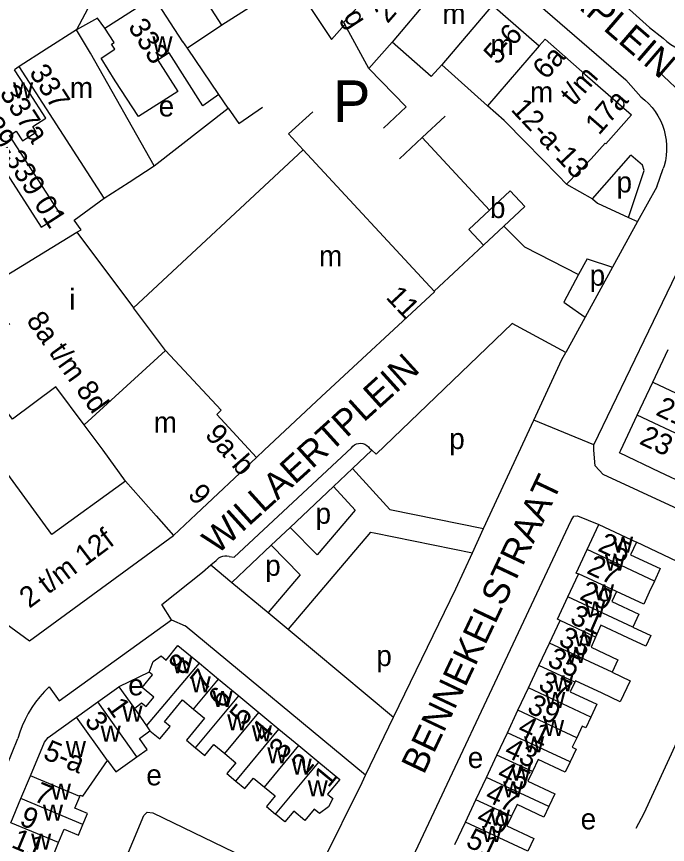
# Model space of a CAD drawing. Extents: x 159045 to 160918, y 380454 to 382516.
# Drawn here: x 160089.8 to 160214.7, y 381424.4 to 381583.2 of the extents above; entities that cross this region are included whole.
import ezdxf

# ---------------------------------------------------------------- set-up
doc = ezdxf.new("R2010")
doc.units = 0
for name, color, linetype in [('BLT_Basislijn', 7, 'Continuous'), ('BLT_Bebouwing', 7, 'Continuous'), ('BLT_Centroide', 7, 'Continuous'), ('BLT_Huisnummer', 7, 'Continuous'), ('BLT_Huisnummer_ tussenligend', 7, 'Continuous'), ('BLT_Huisnummer_reeks', 7, 'Continuous'), ('BLT_Onderverdeling_panden', 7, 'Continuous'), ('BLT_Straatnaam', 7, 'Continuous'), ('BLT_Tekst_parkeren', 7, 'Continuous'), ('BLT_Vlakafsluiter', 7, 'Continuous')]:
    doc.layers.add(name, color=color, linetype=linetype)

msp = doc.modelspace()

# ---------------------------------------------------------------- linework, layer by layer
at = {"layer": 'BLT_Basislijn'}
for p, q in [((160157.41, 381613.8), (160206.67, 381571.07)), ((160204.13, 381587.53), (160211.24, 381581.13)), ((160129.19, 381581.56), (160122.6, 381577.15)), ((160211.24, 381581.13), (160213.86, 381579.05)), ((160090.36, 381573.63), (160089.43, 381573.02)), ((160157.41, 381573.25), (160164.57, 381565.9)), ((160212.8, 381572.8), (160219.11, 381566.84)), ((160206.67, 381571.07), (160209.56, 381567.81)), ((160130.4, 381565.65), (160128.65, 381568.24)), ((160116.19, 381554.56), (160130.4, 381565.65)), ((160164.57, 381565.9), (160160.18, 381561.81)), ((160172.02, 381564.1), (160167.63, 381560.01)), ((160167.63, 381560.01), (160163.24, 381555.92)), ((160180.54, 381546.07), (160167.63, 381560.01)), ((160200.29, 381548.23), (160207.63, 381556.64)), ((160212.61, 381550.57), (160213.85, 381554.04)), ((160195.29, 381551.04), (160200.29, 381548.23)), ((160212.61, 381550.57), (160208.94, 381543.89)), ((160208.94, 381543.89), (160204.15, 381535.17)), ((160207.21, 381544.68), (160208.94, 381543.89)), ((160174.57, 381534.87), (160179.37, 381539.35)), ((160199.27, 381536.71), (160197.59, 381533.74)), ((160204.15, 381535.17), (160198.87, 381525.53)), ((160199.27, 381536.71), (160204.15, 381535.17)), ((160169.89, 381530.52), (160174.57, 381534.87)), ((160197.59, 381533.74), (160194.79, 381528.42)), ((160194.79, 381528.42), (160195.24, 381528.1)), ((160195.24, 381528.1), (160198.87, 381525.53)), ((160198.87, 381525.53), (160195.16, 381518.78)), ((160179.41, 381484.97), (160189.04, 381505.8)), ((160154.04, 381500.5), (160131.59, 381479.5)), ((160157.46, 381500.48), (160157.98, 381500.01)), ((160157.98, 381500.01), (160154.25, 381496.49)), ((160157.98, 381500.01), (160158.77, 381499.28)), ((160154.25, 381496.49), (160150.61, 381493.06)), ((160154.25, 381496.49), (160161.4, 381488.64)), ((160150.61, 381493.06), (160142.3, 381485.22)), ((160161.4, 381488.64), (160179.41, 381484.97)), ((160142.3, 381485.22), (160138.66, 381481.79)), ((160142.3, 381485.22), (160147.47, 381479.95)), ((160177.25, 381480.31), (160179.41, 381484.97)), ((160157.71, 381484.29), (160149.79, 381474.95)), ((160157.71, 381484.29), (160158.43, 381484.14)), ((160158.43, 381484.14), (160177.25, 381480.31)), ((160138.66, 381481.79), (160131.1, 381474.67)), ((160138.66, 381481.79), (160144.22, 381476.12)), ((160130.61, 381479.62), (160131.59, 381479.5)), ((160127.1, 381478), (160128.14, 381478.88)), ((160127.1, 381478), (160131.1, 381474.67)), ((160144.22, 381476.12), (160138.07, 381468.86)), ((160149.79, 381474.95), (160141.92, 381465.66)), ((160131.1, 381474.67), (160138.07, 381468.86)), ((160138.07, 381468.86), (160141.92, 381465.66)), ((160119.55, 381467.48), (160122.14, 381466.34)), ((160156.74, 381437.68), (160122.14, 381466.34)), ((160141.92, 381465.66), (160162.14, 381448.82)), ((160115.27, 381457.42), (160109.47, 381454.65)), ((160156.74, 381437.68), (160162.14, 381448.82)), ((160156.08, 381436.3), (160156.74, 381437.68)), ((160145.99, 381415.93), (160156.08, 381436.3))]:
    msp.add_line(p, q, dxfattribs=at)
for points in [[(160157.41, 381613.8), (160156.17, 381614.66), (160154.62, 381615.42), (160153.06, 381615.89), (160151.26, 381616.13), (160149.47, 381616.06), (160147.8, 381615.72), (160146.17, 381615.11), (160144.91, 381614.4), (160105.09, 381587.84), (160101.3, 381580.69)], [(160106.79, 381581.02), (160105.36, 381582.92), (160101.3, 381580.69)], [(160213.86, 381579.05), (160214.55, 381578.43), (160215.28, 381577.88), (160216.06, 381577.38), (160216.89, 381576.96), (160217.74, 381576.61), (160218.62, 381576.34), (160219.53, 381576.14), (160220.44, 381576.02), (160221.37, 381575.98), (160222.29, 381576.02), (160223.21, 381576.14), (160224.11, 381576.34), (160224.99, 381576.62), (160225.85, 381576.97), (160226.67, 381577.4), (160227.45, 381577.89), (160228.18, 381578.45), (160228.87, 381579.07), (160229.49, 381579.75), (160229.7, 381579.99)], [(160209.56, 381567.81), (160210.33, 381567.19), (160211.04, 381566.51), (160211.7, 381565.77), (160212.3, 381564.99), (160212.83, 381564.15), (160213.3, 381563.28), (160213.69, 381562.37), (160214.01, 381561.43), (160214.25, 381560.48), (160214.41, 381559.5), (160214.49, 381558.52), (160214.49, 381557.53), (160214.42, 381556.54), (160214.26, 381555.57), (160214.03, 381554.6), (160213.85, 381554.04)], [(160130.4, 381565.65), (160132.46, 381562.68), (160136.97, 381565.81)], [(160144.79, 381557.65), (160141.99, 381560.71), (160146.62, 381564.95)], [(160207.21, 381544.68), (160210.22, 381553.68), (160209.86, 381554.72), (160207.63, 381556.64)], [(160101.42, 381541.84), (160102.23, 381542.33), (160100.89, 381544.13), (160106.64, 381548.39)], [(160200.29, 381548.23), (160201.26, 381547.41), (160207.21, 381544.68)], [(160183.29, 381542.99), (160187.22, 381539.02), (160197.59, 381533.74)], [(160355.38, 381430.81), (160353.32, 381428.71), (160352.04, 381428.01), (160348.86, 381427.62), (160346.73, 381427.97), (160263.33, 381467.17), (160202.36, 381495.39), (160200.8, 381497.03), (160200.55, 381500), (160200.57, 381501.03), (160218.14, 381537.53), (160220.13, 381541.34)], [(160195.16, 381518.78), (160184.9, 381524.3), (160158.77, 381499.28)], [(160189.04, 381505.8), (160194.42, 381517.44), (160195.16, 381518.78)], [(160154.04, 381500.5), (160154.32, 381500.8), (160154.65, 381501.05), (160155.03, 381501.22), (160155.43, 381501.32), (160155.84, 381501.35), (160156.25, 381501.29), (160156.64, 381501.15), (160156.99, 381500.94), (160157.3, 381500.67), (160157.46, 381500.48)], [(160150.61, 381493.06), (160154.74, 381488.52), (160147.47, 381479.95)], [(160157.49, 381404.21), (160157.76, 381404.79), (160196.22, 381486.52), (160196.73, 381487.37), (160197.39, 381487.43), (160201.5, 381485.76)], [(160229.59, 381472.48), (160208.73, 381482.37)], [(160130.61, 381479.62), (160130.18, 381479.71), (160129.75, 381479.72), (160129.33, 381479.65), (160128.92, 381479.5), (160128.55, 381479.28), (160128.23, 381478.99), (160128.14, 381478.88)], [(160162.14, 381448.82), (160174.06, 381473.41), (160177.25, 381480.31)], [(160119.55, 381467.48), (160117.68, 381470.43), (160125.46, 381476.6), (160127.1, 381478)], [(160208.66, 381427.53), (160210.22, 381430.4), (160229.59, 381472.48)], [(160096.09, 381454.64), (160097.99, 381451.96), (160119.55, 381467.48)], [(160096.09, 381454.64), (160095.16, 381453.71), (160094.29, 381452.73), (160093.48, 381451.71), (160092.74, 381450.63), (160092.06, 381449.51), (160091.45, 381448.35), (160090.92, 381447.15), (160090.45, 381445.93), (160090.07, 381444.68)], [(160079.79, 381419.45), (160087.89, 381439.37), (160090.07, 381444.68)], [(160105.8, 381409.71), (160114.24, 381429.92), (160114.85, 381430.58), (160115.99, 381430.46), (160135.38, 381421.05), (160141.4, 381418.18), (160145.99, 381415.93)]]:
    msp.add_lwpolyline(points, dxfattribs=at)
at = {"layer": 'BLT_Bebouwing'}
for p, q in [((160142.71, 381590.17), (160129.19, 381581.56)), ((160142.71, 381590.17), (160150.2, 381578.82)), ((160106.79, 381581.02), (160116.12, 381586.99)), ((160181.13, 381585.43), (160190.08, 381577.61)), ((160152.76, 381581.67), (160150.2, 381578.82)), ((160157.41, 381573.25), (160152.76, 381581.67)), ((160101.3, 381580.69), (160095.51, 381576.95)), ((160122.6, 381577.15), (160121.73, 381578.43)), ((160095.51, 381576.95), (160090.36, 381573.63)), ((160128.65, 381568.24), (160122.6, 381577.15)), ((160180.17, 381566.08), (160171.36, 381573.99)), ((160111.4, 381551.47), (160116.19, 381554.56)), ((160195.29, 381551.04), (160193.68, 381552.7)), ((160106.64, 381548.39), (160111.4, 381551.47)), ((160187.33, 381546.75), (160183.29, 381542.99)), ((160176.55, 381542.36), (160180.54, 381546.07)), ((160083.59, 381530.95), (160101.42, 381541.84)), ((160101.42, 381541.84), (160112.26, 381527.32)), ((160176.55, 381542.36), (160179.37, 381539.35)), ((160183.29, 381542.99), (160179.37, 381539.35)), ((160169.98, 381530.43), (160148.32, 381510.31)), ((160169.89, 381530.52), (160169.98, 381530.43)), ((160211.88, 381513.1), (160214.81, 381519.32)), ((160208.87, 381506.72), (160211.88, 381513.1)), ((160102.77, 381504.92), (160097.35, 381512.17)), ((160103.15, 381504.4), (160102.77, 381504.92)), ((160226.96, 381489.34), (160213.22, 381495.83)), ((160124.27, 381487.74), (160119.94, 381483.68)), ((160199.26, 381480.98), (160201.5, 381485.76)), ((160201.5, 381485.76), (160208.73, 381482.37)), ((160195.55, 381471.88), (160197.58, 381476.22)), ((160192.03, 381463.01), (160194.07, 381467.36)), ((160190.02, 381458.72), (160192.03, 381463.01)), ((160124.89, 381459.15), (160128.56, 381456.11)), ((160188, 381454.42), (160190.02, 381458.72)), ((160128.56, 381456.11), (160132.44, 381452.9)), ((160105.42, 381451.72), (160109.47, 381454.65)), ((160109.47, 381454.65), (160112.46, 381450.45)), ((160185.99, 381450.13), (160188, 381454.42)), ((160132.44, 381452.9), (160136.3, 381449.71)), ((160101.35, 381448.81), (160105.42, 381451.72)), ((160136.3, 381449.71), (160140.13, 381446.53)), ((160183.97, 381445.83), (160185.99, 381450.13)), ((160140.13, 381446.53), (160143.95, 381443.37)), ((160181.96, 381441.54), (160183.97, 381445.83)), ((160143.95, 381443.37), (160147.81, 381440.18)), ((160179.95, 381437.25), (160181.96, 381441.54)), ((160090.68, 381433.18), (160092.49, 381437.54)), ((160177.93, 381432.95), (160179.95, 381437.25)), ((160088.76, 381428.54), (160090.68, 381433.18)), ((160175.92, 381428.66), (160177.93, 381432.95)), ((160173.91, 381424.36), (160175.92, 381428.66))]:
    msp.add_line(p, q, dxfattribs=at)
for points in [[(160129.19, 381581.56), (160122.81, 381591.56), (160122.67, 381591.47), (160121.35, 381593.53)], [(160116.12, 381586.99), (160121.64, 381578.37), (160121.73, 381578.43)], [(160116.19, 381554.56), (160103.99, 381576.21), (160101.3, 381580.69)], [(160128.65, 381568.24), (160125.54, 381566.11), (160119.08, 381576.24), (160116.92, 381574.87), (160120.76, 381568.84), (160113.2, 381564.03), (160108.74, 381570.91), (160106.05, 381575.26), (160108.69, 381576.94), (160108.06, 381577.94), (160108.55, 381578.26), (160106.79, 381581.02)], [(160161.85, 381578.33), (160157.41, 381573.25)], [(160171.36, 381573.99), (160169.37, 381571.73), (160161.85, 381578.33)], [(160190.08, 381577.61), (160191.18, 381578.88), (160198.84, 381572.19)], [(160106.64, 381548.39), (160090.36, 381573.63)], [(160089.78, 381561.23), (160090.99, 381559.36), (160093.61, 381561.05), (160092.93, 381562.1), (160095.43, 381563.71), (160092.28, 381568.58), (160089.43, 381573.02)], [(160198.84, 381572.19), (160207.77, 381564.39), (160202.87, 381558.78), (160202.69, 381558.94), (160200.03, 381555.9), (160195.29, 381551.04)], [(160187.43, 381559.12), (160183.36, 381563.3), (160180.17, 381566.08)], [(160085.82, 381556.34), (160094.56, 381542.8), (160098.3, 381545.21), (160088.49, 381560.4), (160089.78, 381561.23)], [(160193.68, 381552.7), (160187.43, 381559.12)], [(160112.26, 381527.32), (160144.79, 381557.65)], [(160144.79, 381557.65), (160169.89, 381530.52)], [(160180.54, 381546.07), (160184.52, 381549.78), (160187.33, 381546.75)], [(160097.35, 381512.17), (160089.07, 381505.98), (160080.1, 381517.99), (160088.55, 381524.3)], [(160148.32, 381510.31), (160137.34, 381500), (160135.85, 381498.6)], [(160213.22, 381495.83), (160205.46, 381499.5), (160205.69, 381500), (160208.87, 381506.72)], [(160110.69, 381494.11), (160106.44, 381500), (160103.15, 381504.4)], [(160135.85, 381498.6), (160124.27, 381487.74)], [(160110.69, 381494.11), (160096.57, 381483.82), (160087.45, 381496.36), (160071.9, 381485.02), (160084.11, 381469.42)], [(160084.11, 381469.42), (160092.31, 381463.48), (160119.94, 381483.68)], [(160208.73, 381482.37), (160207.6, 381479.96), (160213.29, 381477.3), (160212.17, 381474.92)], [(160197.58, 381476.22), (160197.13, 381476.43), (160199.26, 381480.98)], [(160212.17, 381474.92), (160211.17, 381472.78), (160210.1, 381470.51), (160204.9, 381472.93)], [(160194.07, 381467.36), (160193.55, 381467.61), (160195.55, 381471.88)], [(160204.9, 381472.93), (160203.99, 381470.99), (160209.17, 381468.55), (160208.01, 381466.07)], [(160208.01, 381466.07), (160211.45, 381464.46), (160210.49, 381462.4), (160207.04, 381464.02), (160201.85, 381466.45), (160200.87, 381464.18)], [(160200.87, 381464.18), (160200.02, 381462.24), (160205.17, 381459.83), (160204.04, 381457.41)], [(160115.27, 381457.42), (160116, 381459.46), (160117.57, 381460.54), (160118.49, 381459.77), (160120.79, 381462.55), (160124.89, 381459.15)], [(160114.66, 381450.83), (160116.16, 381452.65), (160113.92, 381454.51), (160115.9, 381456.9), (160115.27, 381457.42)], [(160204.04, 381457.41), (160207.49, 381455.79), (160205.6, 381451.77), (160202.15, 381453.38), (160197.01, 381455.78), (160196.88, 381455.52)], [(160196.88, 381455.52), (160196.02, 381453.67), (160201.14, 381451.27), (160199.99, 381448.83)], [(160112.46, 381450.45), (160113.77, 381451.57), (160114.66, 381450.83)], [(160118.19, 381447.9), (160121.67, 381452.1), (160123.78, 381450.34)], [(160123.78, 381450.34), (160125.9, 381448.59), (160122.39, 381444.36), (160124.15, 381442.9)], [(160092.49, 381437.54), (160095.18, 381443.99), (160095.9, 381444.93), (160101.35, 381448.81)], [(160115.42, 381446.17), (160117.29, 381444.62), (160119.26, 381447.01), (160118.19, 381447.9)], [(160199.99, 381448.83), (160199.02, 381446.76), (160198.31, 381447.09), (160197.26, 381444.87)], [(160112.91, 381441.21), (160114.89, 381442.62), (160113.39, 381444.72), (160115.42, 381446.17)], [(160197.26, 381444.87), (160196.4, 381443.02), (160197.12, 381442.68), (160195.98, 381440.24)], [(160124.15, 381442.9), (160125.91, 381441.44), (160127.66, 381443.55), (160129.76, 381441.81)], [(160129.76, 381441.81), (160131.86, 381440.07), (160130.13, 381437.98), (160131.87, 381436.54)], [(160101.95, 381433.58), (160102.05, 381433.82), (160102.52, 381433.62), (160107.29, 381440.48)], [(160107.29, 381440.48), (160108.84, 381438.3), (160112.91, 381441.21)], [(160147.81, 381440.18), (160151.8, 381436.87), (160149.44, 381434.02), (160150.46, 381433.17), (160149.64, 381431.57), (160147.91, 381430.32), (160146.88, 381431.17), (160145.09, 381429.01), (160142.99, 381430.75), (160141.29, 381428.7), (160139.52, 381430.17)], [(160195.98, 381440.24), (160195.03, 381438.23), (160189.85, 381440.66), (160188.77, 381438.36)], [(160188.77, 381438.36), (160187.91, 381436.53), (160193.06, 381434.11), (160191.92, 381431.67)], [(160131.87, 381436.54), (160133.61, 381435.1), (160135.28, 381437.12), (160137.36, 381435.4)], [(160137.36, 381435.4), (160139.44, 381433.68), (160137.75, 381431.64), (160139.52, 381430.17)], [(160102.56, 381428.24), (160103.43, 381430.33), (160101.02, 381431.34), (160101.95, 381433.58)], [(160191.92, 381431.67), (160190.97, 381429.64), (160185.81, 381432.06), (160184.74, 381429.78)], [(160184.74, 381429.78), (160183.88, 381427.95), (160189.06, 381425.52), (160187.91, 381423.07)], [(160097.88, 381424.75), (160098.93, 381427.29), (160101.69, 381426.15), (160102.56, 381428.24)], [(160099.06, 381418.78), (160100.28, 381418.27), (160101.17, 381420.4), (160096.82, 381422.21), (160097.88, 381424.75)]]:
    msp.add_lwpolyline(points, dxfattribs=at)
at = {"layer": 'BLT_Onderverdeling_panden'}
for p, q in [((160173.49, 381592.11), (160161.85, 381578.33)), ((160181.13, 381585.43), (160171.36, 381573.99)), ((160190.08, 381577.61), (160180.17, 381566.08)), ((160118.39, 381519.14), (160112.26, 381527.32)), ((160118.39, 381519.14), (160102.77, 381504.92)), ((160135.85, 381498.6), (160128.23, 381506.88)), ((160230.37, 381496.67), (160208.87, 381506.72)), ((160212.17, 381474.92), (160199.26, 381480.98)), ((160208.01, 381466.07), (160195.55, 381471.88)), ((160200.87, 381464.18), (160194.07, 381467.36)), ((160204.04, 381457.41), (160192.03, 381463.01)), ((160114.73, 381447.17), (160124.89, 381459.15)), ((160196.88, 381455.52), (160190.02, 381458.72)), ((160123.78, 381450.34), (160128.56, 381456.11)), ((160199.99, 381448.83), (160188, 381454.42)), ((160124.15, 381442.9), (160132.44, 381452.9)), ((160112.91, 381441.21), (160105.42, 381451.72)), ((160112.46, 381450.45), (160114.73, 381447.17)), ((160129.76, 381441.81), (160136.3, 381449.71)), ((160197.26, 381444.87), (160185.99, 381450.13)), ((160107.29, 381440.48), (160101.35, 381448.81)), ((160114.73, 381447.17), (160115.42, 381446.17)), ((160131.87, 381436.54), (160140.13, 381446.53)), ((160195.98, 381440.24), (160183.97, 381445.83)), ((160137.36, 381435.4), (160143.95, 381443.37)), ((160188.77, 381438.36), (160181.96, 381441.54)), ((160139.52, 381430.17), (160147.81, 381440.18)), ((160101.95, 381433.58), (160092.49, 381437.54)), ((160191.92, 381431.67), (160179.95, 381437.25)), ((160102.56, 381428.24), (160090.68, 381433.18)), ((160184.74, 381429.78), (160177.93, 381432.95)), ((160097.88, 381424.75), (160088.76, 381428.54)), ((160187.91, 381423.07), (160175.92, 381428.66))]:
    msp.add_line(p, q, dxfattribs=at)
for points in [[(160166.85, 381597.9), (160152.54, 381582.09), (160152.76, 381581.67)], [(160128.23, 381506.88), (160129.09, 381507.73), (160118.39, 381519.14)], [(160211.88, 381513.1), (160226.34, 381506.26), (160225.99, 381505.5), (160232.93, 381502.14)], [(160110.69, 381494.11), (160116.63, 381487.43), (160119.94, 381483.68)], [(160204.9, 381472.93), (160197.63, 381476.32), (160197.58, 381476.22)]]:
    msp.add_lwpolyline(points, dxfattribs=at)
at = {"layer": 'BLT_Vlakafsluiter'}
msp.add_line((160200.57, 381501.03), (160189.04, 381505.8), dxfattribs=at)

# ---------------------------------------------------------------- texts
at = {"layer": 'BLT_Centroide'}
for s, p in [('m', (160171.48, 381581.78)), ('w', (160115.88, 381576.34)), ('m', (160180.72, 381575.83)), ('w', (160089.16, 381567.52)), ('m', (160100.04, 381567.59)), ('m', (160188.29, 381566.75)), ('e', (160117.08, 381564.05)), ('p', (160204.89, 381549.47)), ('b', (160180.62, 381544.56)), ('m', (160147.84, 381535.31)), ('p', (160199.74, 381531.59)), ('i', (160099.94, 381526.98)), ('m', (160116.13, 381503.41)), ('p', (160172.81, 381500.24)), ('p', (160147.17, 381485.91)), ('w', (160204.2, 381480.34)), ('w', (160202.67, 381476.88)), ('p', (160137.52, 381475.92)), ('w', (160200.55, 381471.19)), ('w', (160198.84, 381467.94)), ('w', (160196.73, 381462.38)), ('w', (160195.23, 381459.19)), ('p', (160158.83, 381458.6)), ('w', (160119.67, 381457.23)), ('e', (160111.24, 381452.99)), ('w', (160123.22, 381453.59)), ('w', (160192.73, 381453.78)), ('w', (160127.41, 381450.78)), ('w', (160191.21, 381450.59)), ('w', (160110.13, 381447.97)), ('w', (160130.22, 381446.3)), ('w', (160190.98, 381445.19)), ('w', (160105.95, 381444.11)), ('w', (160134.95, 381444.16)), ('w', (160187.16, 381442.03)), ('w', (160099.27, 381441.14)), ('w', (160137.91, 381439.95)), ('e', (160176.36, 381439.05)), ('w', (160142.58, 381437.8)), ('e', (160114.71, 381435.72)), ('w', (160184.64, 381436.59)), ('w', (160145.66, 381433.64)), ('w', (160096.41, 381433)), ('w', (160183.13, 381433.44)), ('w', (160094.88, 381428.97)), ('w', (160180.61, 381428)), ('e', (160198.01, 381427.28)), ('w', (160179.09, 381424.88)), ('w', (160092.62, 381423.41))]:
    msp.add_text(s, height=4, dxfattribs=at).set_placement(p)
at = {"layer": 'BLT_Huisnummer'}
for s, rotation, p in [('333', 302.4949, (160111.1, 381581.28)), ('337', 302.833, (160092.14, 381572.48)), ('337a', 302.8324, (160086.46, 381568.55)), ('21', 334.7248, (160212.22, 381506.88)), ('23', 334.7248, (160209.07, 381501.33)), ('25', 334.8701, (160201.11, 381480.8)), ('29', 336.5968, (160197.6, 381471.51)), ('33', 334.8721, (160193.54, 381462.78)), ('8', 50.3614, (160121.71, 381456.65)), ('7', 50.3727, (160125.9, 381453.6)), ('37', 334.8693, (160189.66, 381454.25)), ('6', 50.3683, (160129.31, 381450.24)), ('1', 305.4933, (160106.96, 381450.8)), ('5', 50.374, (160133.4, 381446.94)), ('4', 50.3829, (160137.47, 381443.85)), ('41', 334.8841, (160185.7, 381445.69)), ('3', 50.3711, (160140.98, 381440.48)), ('2', 50.374, (160145.23, 381437.51)), ('45', 334.8651, (160181.76, 381437.02)), ('1', 50.3729, (160149.62, 381435.13)), ('9', 337.4252, (160090.18, 381428.22)), ('49', 334.8682, (160177.78, 381428.58))]:
    msp.add_text(s, height=4, rotation=rotation, dxfattribs=at).set_placement(p)
at = {"layer": 'BLT_Huisnummer_ tussenligend'}
for s, rotation, p in [('27', 334.8701, (160198.96, 381476.52)), ('31', 336.5968, (160195.73, 381466.9)), ('35', 334.8721, (160191.4, 381458.78)), ('39', 334.8693, (160187.52, 381449.82)), ('3', 305.4886, (160102.73, 381448.13)), ('43', 334.8841, (160183.15, 381441.45)), ('7', 337.4262, (160092.9, 381432.82)), ('47', 334.8651, (160179.46, 381432.88)), ('51', 334.8682, (160175.77, 381424.1)), ('11', 337.4252, (160088.62, 381423.91))]:
    msp.add_text(s, height=4, rotation=rotation, dxfattribs=at).set_placement(p)
at = {"layer": 'BLT_Huisnummer_reeks'}
for s, rotation, p in [('323-a t/m g', 303.4131, (160139.13, 381603.26)), ('2-c-d-3', 48.9641, (160160.98, 381581.76)), ('5-6', 49.3321, (160182.05, 381573.78)), ('6a', 48.8489, (160191.43, 381570.93)), ('t/m', 48.8489, (160196.72, 381565.92)), ('12-a-13', 313.1791, (160184.48, 381565.27)), ('17a', 48.8553, (160201.51, 381560.3)), ('339-339 01', 302.8331, (160081.61, 381565)), ('11', 313.2029, (160160.48, 381529.27)), ('8a t/m 8d', 305.5593, (160091.57, 381524.88)), ('9a-b', 311.4495, (160125.79, 381502.88)), ('9', 311.4495, (160122.5, 381491.41)), ('2 t/m 12f', 37, (160092.28, 381469.57)), ('5-a', 337.4262, (160094.7, 381440.91))]:
    msp.add_text(s, height=4, rotation=rotation, dxfattribs=at).set_placement(p)
at = {"layer": 'BLT_Straatnaam'}
for s, height, rotation, p in [('FRANZ LEHARPLEIN', 4.9999, 319.259, (160163.61, 381613.98)), ('WILLAERTPLEIN', 5, 42.0999, (160128.29, 381479.86)), ('BENNEKELSTRAAT', 5, 64.6455, (160167.93, 381437.63))]:
    msp.add_text(s, height=height, rotation=rotation, dxfattribs=at).set_placement(p)
at = {"layer": 'BLT_Tekst_parkeren'}
msp.add_text('P', height=8, dxfattribs=at).set_placement((160150.55, 381562.97))

doc.saveas('drawing.dxf')
